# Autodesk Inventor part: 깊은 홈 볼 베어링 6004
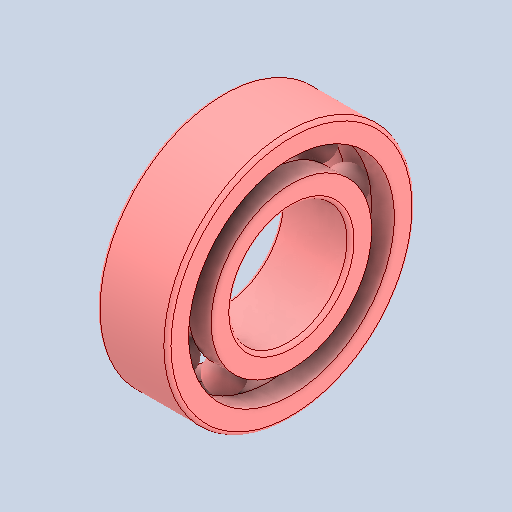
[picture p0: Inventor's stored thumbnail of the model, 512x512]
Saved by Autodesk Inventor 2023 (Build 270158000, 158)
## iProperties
Created: 2026-03
Part Number: 깊은 홈 볼 베어링 6004
Material: 강철, 연강
Description: 깊은 그루브 볼 베어링
Document SubType Name: Modeling
Designer: 4강의실
Density: 7.85 g/cm^3
Appearance: 기본값
Author: jhkim
Sending System: Autodesk Inventor 2026
Preprocessor: ST-DEVELOPER v20.1
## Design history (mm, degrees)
feature "Solid1"
feature "Solid1:1"
feature "Solid1:2"
feature "Solid1:3"
feature "Solid1:4"
feature "Solid1:5"
feature "Solid1:6"
feature "Solid1:7"
feature "Solid1:8"
feature "Solid1:9"
feature "Solid1:10"
node "솔리드1"
node "솔리드2"
node "솔리드3"
node "솔리드4"
node "솔리드5"
node "솔리드6"
node "솔리드7"
node "솔리드8"
node "솔리드9"
node "솔리드10"
node "솔리드11"
